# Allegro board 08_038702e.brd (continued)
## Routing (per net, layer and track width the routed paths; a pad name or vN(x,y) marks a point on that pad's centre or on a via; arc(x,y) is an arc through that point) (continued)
IO_L18_34_JX4_N: length 72.1
  TOP w0.089: U1.A7 v1(47.22,37.59)
  L6_SIG w0.089: v1(80.19,23.48) 80.06,23.6 79.3,23.6 78.92,23.22 78.92,20.3 78.54,19.92 77.78,19.92 77.4,20.3 77.4,22.33 77.01,22.71 75.36,22.71 74.98,23.1 74.98,23.98 75.36,24.37 77.67,24.37 77.9,24.6 77.9,25.35 77.67,25.58 75.64,25.58 75.11,26.11 75.11,26.76 75.64,27.29 79.19,27.29 79.43,27.52 79.43,28.58 79.19,28.81 75.64,28.81 75.11,29.34 75.11,30.69 75.64,31.22 77.54,31.22 77.78,31.46 77.78,32.39 77.54,32.62 75.74,32.62 72.77,35.59 72.75,35.59 72.67,35.67 71.32,35.67 70.05,36.94 60.6,36.94 60.52,37.02 60.24,37.02 60.16,36.94 58.49,36.94 57.73,37.7 51.69,37.7 51.53,37.54 50.45,37.54 50.29,37.7 49.81,37.7 49.43,37.32 48.21,37.32 47.57,37.95 46.94,37.95 46.74,37.75 46.74,37.5 46.8,37.43 47.06,37.43 v1(47.22,37.59)
  BOTTOM w0.089: JX4.70 80.68,23.37 80.44,23.6 80.32,23.6 v1(80.19,23.48)
IO_L18_34_JX4_P: length 72.2
  TOP w0.089: U1.B7 v1(46.22,37.59)
  L6_SIG w0.089: v1(80.19,23.98) 80.06,23.86 79.19,23.86 78.67,23.33 78.67,20.41 78.43,20.17 77.88,20.17 77.65,20.41 77.65,22.44 77.12,22.97 75.47,22.97 75.24,23.2 75.24,23.88 75.47,24.11 77.78,24.11 78.16,24.49 78.16,25.45 77.78,25.84 75.74,25.84 75.36,26.22 75.36,26.65 75.74,27.03 79.3,27.03 79.68,27.41 79.68,28.68 79.3,29.06 75.74,29.06 75.36,29.45 75.36,30.59 75.74,30.97 77.65,30.97 78.03,31.35 78.03,32.49 77.65,32.87 75.85,32.87 72.88,35.85 72.86,35.85 72.78,35.92 71.43,35.92 70.16,37.19 60.7,37.19 60.62,37.27 60.13,37.27 60.05,37.19 58.6,37.19 57.84,37.95 51.79,37.95 51.53,38.21 50.45,38.21 50.26,38.02 50.26,37.99 50.22,37.95 49.71,37.95 49.33,37.57 48.31,37.57 47.68,38.21 46.84,38.21 v1(46.22,37.59)
  BOTTOM w0.089: JX4.68 80.76,24.17 80.44,23.86 80.32,23.86 v1(80.19,23.98)
IO_L18_35_TX_D5_N: length 29.6
  TOP w0.089: U1.A17 v1(47.22,26.59) ; v6(63.6,28.89) U17.F8
  L15_SIG w0.089: v1(47.22,26.59) 47.15,26.52 46.92,26.52 46.78,26.66 46.78,26.9 46.84,26.96 47.64,26.96 49.22,25.38 49.35,25.38 50.26,24.48 50.26,24.17 50.45,23.98 50.75,23.98 52.4,22.33 58.63,22.33 58.75,22.21 62.41,22.21 64.95,24.75 64.95,26.04 65.31,26.4 65.31,26.98 65.5,27.17 65.5,27.42 65.31,27.6 65.31,27.68 65.31,27.68 65.31,28.07 64.57,28.81 64.13,28.81 63.9,28.57 63.9,28.52 63.81,28.45 63.71,28.45 63.6,28.56 v6(63.6,28.89)
IO_L18_35_TX_D5_P: length 28.3
  TOP w0.089: v6(64.4,28.09) U17.E7 ; U1.B17 v1(46.22,26.59)
  L15_SIG w0.089: v6(64.4,28.09) 64.15,28.34 64.15,28.47 64.24,28.56 64.44,28.56 65.05,27.94 65.05,27.57 64.9,27.42 64.9,27.17 65.05,27.01 65.05,26.5 64.7,26.14 64.7,24.85 62.3,22.46 58.86,22.46 58.73,22.59 52.5,22.59 50.93,24.16 50.93,24.45 50.73,24.65 50.44,24.65 49.46,25.64 49.33,25.64 47.75,27.22 46.59,27.22 46.22,26.84 v1(46.22,26.59)
IO_L19_12_JX2_N: length 74.3
  TOP w0.089: U1.AA17 v1(26.22,26.59)
  L15_SIG w0.089: v1(66.22,5.19) 66.22,4.19 65.38,3.36 65.38,3.36 65.05,3.03 64.93,3.03 63.28,1.38 35.23,1.38 32.18,4.43 32.18,4.48 32.1,4.56 32.1,5.05 32.18,5.13 32.18,7.98 29.77,10.4 28.02,10.4 27.52,10.9 22.81,10.9 21.77,11.94 21.77,16.72 22.3,17.25 22.35,17.25 22.55,17.45 22.55,24.73 22.53,24.75 22.53,25.43 22.55,25.45 22.55,25.76 23.04,26.25 25.57,26.25 25.6,26.22 26.41,26.22 26.53,26.33 26.53,26.46 26.47,26.52 26.28,26.52 v1(26.22,26.59)
  BOTTOM w0.089: JX2.90 66.33,5.8 66.05,5.53 66.05,5.35 v1(66.22,5.19)
IO_L19_12_JX2_P: length 74.4
  TOP w0.089: U1.Y17 v1(27.22,26.59)
  L15_SIG w0.089: v1(27.22,26.59) 26.85,26.59 26.79,26.52 26.79,26.23 26.52,25.96 25.5,25.96 25.46,26 23.15,26 22.81,25.66 22.81,25.34 22.79,25.32 22.79,24.85 22.81,24.83 22.81,17.34 22.46,17 22.4,17 22.02,16.62 22.02,12.05 22.91,11.16 27.62,11.16 28.13,10.65 29.88,10.65 32.44,8.09 32.44,5.03 32.36,4.95 32.36,4.67 32.44,4.59 32.44,4.53 35.34,1.63 63.17,1.63 64.82,3.28 64.95,3.28 65.97,4.3 65.97,4.43 65.71,4.68 65.46,4.68 65.33,4.81 65.33,5.06 65.46,5.19 v1(65.71,5.19)
  BOTTOM w0.089: v1(65.71,5.19) 65.84,5.32 65.84,5.57 65.53,5.88 JX2.88
IO_L19_13_JX2_N: length 74
  TOP w0.089: U1.Y20 v1(27.22,23.59)
  L15_SIG w0.089: v1(27.22,23.59) 27.35,23.45 27.48,23.45 27.59,23.35 27.59,22.46 27.31,22.18 26.97,22.18 26.55,21.76 26.55,21.45 26.29,21.19 25.96,21.19 25.58,20.81 25.58,17.48 25.55,17.46 25.55,17.45 25.07,16.97 25.07,15.37 26.11,14.33 29.11,14.33 29.75,14.97 31.06,14.97 31.7,14.33 37.14,14.33 39.17,12.3 39.17,10.03 39.46,9.73 39.46,9.49 40.42,8.53 40.8,8.53 42.36,6.97 43.97,6.97 44.73,7.73 45.92,7.73 46.15,7.5 46.15,5.85 46.68,5.32 47.78,5.32 48.31,5.85 48.31,9.99 47.78,10.52 40.92,10.52 40.69,10.75 40.69,11.06 40.92,11.28 49.22,11.28 49.46,11.05 49.46,10.16 49.98,9.63 50.6,9.63 51.36,10.4 55.17,10.4 55.81,11.03 v1(55.81,12.3)
  BOTTOM w0.089: JX2.63 55.93,11.67 55.68,11.92 55.68,12.17 v1(55.81,12.3)
IO_L19_13_JX2_P: length 74
  TOP w0.089: U1.W20 v1(28.22,23.59)
  L15_SIG w0.089: v1(55.3,12.3) 55.42,12.17 55.42,12.05 55.36,11.98 54.98,11.98 54.92,11.92 54.92,11.79 55.04,11.67 55.3,11.67 55.55,11.41 55.55,11.14 55.06,10.65 51.25,10.65 50.49,9.89 50.09,9.89 49.71,10.27 49.71,11.16 49.33,11.54 40.81,11.54 40.44,11.17 40.44,10.64 40.81,10.27 47.68,10.27 48.06,9.89 48.06,5.95 47.68,5.57 46.79,5.57 46.41,5.95 46.41,7.6 46.03,7.98 44.63,7.98 43.87,7.22 42.47,7.22 40.9,8.79 40.52,8.79 39.72,9.59 39.72,9.84 39.42,10.13 39.42,12.41 37.24,14.59 31.8,14.59 31.17,15.22 29.64,15.22 29.01,14.59 26.21,14.59 25.33,15.48 25.33,16.86 25.81,17.34 25.81,17.35 25.83,17.38 25.83,20.7 26.07,20.94 26.4,20.94 26.88,21.42 26.88,21.73 27.08,21.92 27.41,21.92 27.84,22.36 27.84,23.22 v1(28.22,23.59)
  BOTTOM w0.089: JX2.61 55.13,11.61 55.46,11.94 55.46,12.14 v1(55.3,12.3)
IO_L19_33_JX1_N: length 73
  TOP w0.089: U1.L7 v1(37.22,37.59)
  L18_SIG w0.089: v1(38.28,49.64) 38.04,49.4 38.04,48.96 38.55,48.45 38.55,47.46 38.17,47.08 37.63,47.08 37.61,47.1 36.35,47.1 35.82,47.63 35.82,48.6 36.5,49.28 36.5,49.87 36.9,50.27 41.09,50.27 41.2,50.38 41.2,51.18 41.09,51.29 36.12,51.29 35.59,51.82 35.59,53.19 35.34,53.45 34.34,53.45 34.09,53.19 34.09,49.89 33.99,49.79 33.99,49.51 34.09,49.42 34.09,49.13 34.47,48.75 34.47,46.7 34.82,46.35 34.82,46.1 35.21,45.7 37.26,45.7 37.52,45.96 37.52,46.21 37.77,46.46 38.83,46.46 39.09,46.21 39.09,44.1 38.81,43.82 38.81,32.34 38.46,32 38.44,32 38.43,31.99 37.91,31.99 37.55,32.35 37.55,44.34 37.33,44.56 37.02,44.56 36.81,44.34 36.81,40.58 36.84,40.54 36.84,37.96 v1(37.22,37.59)
  BOTTOM w0.089: JX1.20 38.33,50.32 38.03,50.02 38.03,49.89 v1(38.28,49.64)
IO_L19_33_JX1_P: length 73
  TOP w0.089: U1.M7 v1(36.22,37.59)
  L18_SIG w0.089: v1(36.22,37.59) 36.59,37.96 36.59,40.44 36.55,40.47 36.55,44.45 36.92,44.81 37.44,44.81 37.81,44.45 37.81,32.45 38.02,32.24 38.32,32.24 38.33,32.25 38.35,32.25 38.55,32.45 38.55,43.73 38.53,43.75 38.53,43.9 38.83,44.2 38.83,46.1 38.73,46.21 37.88,46.21 37.77,46.1 37.77,45.85 37.37,45.45 35.1,45.45 34.56,45.99 34.56,46.24 34.22,46.59 34.22,48.64 33.83,49.03 33.83,49.31 33.74,49.41 33.74,49.9 33.83,50 33.83,53.3 34.24,53.7 35.44,53.7 35.85,53.3 35.85,51.92 36.23,51.54 41.2,51.54 41.45,51.29 41.45,50.27 41.2,50.02 37.01,50.02 36.76,49.77 36.76,49.18 36.07,48.5 36.07,47.73 36.45,47.35 37.71,47.35 37.73,47.33 38.06,47.33 38.3,47.57 38.3,48.35 37.79,48.86 37.79,49.4 v1(37.56,49.64)
  BOTTOM w0.089: JX1.18 37.53,50.26 37.81,49.98 37.81,49.89 v1(37.56,49.64)
IO_L19_34_JX4_N: length 73.3
  TOP w0.089: U1.C3 v1(45.22,41.59)
  L6_SIG w0.089: v1(84.51,21.06) 88.7,21.06 89.33,21.7 89.33,41 88.95,41.38 87.51,41.38 87.5,41.37 87.16,41.37 87.15,41.38 85.4,41.38 85.14,41.64 84.01,41.64 83.75,41.37 81.7,41.37 81.44,41.64 79.83,41.64 79.58,41.38 78.14,41.38 77.5,40.75 75.21,40.75 74.45,41.51 63.93,41.51 63.04,42.4 61.9,42.4 60.76,41.26 57.33,41.26 57.17,41.41 55.2,41.41 55.04,41.26 52.73,41.26 52.52,41.47 52.24,41.47 52.19,41.41 49.65,41.41 49.45,41.22 45.59,41.22 v1(45.22,41.59)
  BOTTOM w0.089: v1(84.51,21.06) 84.63,21.19 84.89,21.19 85.11,20.97 JX4.75
IO_L19_34_JX4_P: length 73.2
  TOP w0.089: U1.C4 v1(45.22,40.59)
  L6_SIG w0.089: v1(45.22,40.59) 45.59,40.96 49.43,40.96 49.65,40.74 52.5,40.74 52.76,41 54.99,41 55.25,40.74 57.13,40.74 57.39,41 60.86,41 62.01,42.15 62.94,42.15 63.83,41.26 74.35,41.26 75.11,40.49 77.61,40.49 78.24,41.13 79.68,41.13 79.94,41.38 81.33,41.38 81.6,41.12 83.85,41.12 84.12,41.38 85.04,41.38 85.29,41.13 87.05,41.13 87.06,41.12 87.6,41.12 87.61,41.13 88.85,41.13 89.08,40.9 89.08,21.8 88.59,21.32 85.27,21.32 85.14,21.44 85.14,21.83 85.02,21.95 84.76,21.95 v1(84.51,21.7)
  BOTTOM w0.089: JX4.73 85.22,21.77 84.89,21.44 84.76,21.44 v1(84.51,21.7)
IO_L19_35_CTRL_OUT0: length 27.6
  TOP w0.14: v6(67.6,27.29) U17.D4 ; U1.D13 v1(44.22,31.59)
  L14_SIG w0.095: v1(44.22,31.59) 44.88,30.93 45.36,30.93 45.57,30.72 46.41,30.72 47.19,29.93 51.77,29.93 52.25,29.45 54.28,29.45 54.28,29.45 54.42,29.45 54.62,29.65 54.62,29.78 55.3,30.46 55.42,30.46 55.45,30.48 55.91,30.48 55.93,30.46 57.33,30.46 58.61,29.18 58.61,29.09 59.11,28.59 64.52,28.59 64.61,28.68 65.71,28.68 66,28.39 66.12,28.39 66.3,28.22 66.3,28.1 66.8,27.59 66.92,27.59 67.22,27.29 v6(67.6,27.29)
IO_L19_35_CTRL_OUT1: length 25.6
  TOP w0.14: v6(67.6,28.09) U17.E4 ; U1.C13 v1(45.22,31.59)
  L14_SIG w0.095: v1(45.22,31.59) 45.71,31.1 47.3,31.1 48.06,30.33 53.42,30.33 53.46,30.29 54.49,30.29 54.92,30.72 57.08,30.72 57.11,30.68 57.49,30.68 58.16,30.01 58.16,29.97 58.49,29.65 58.53,29.65 58.85,29.32 65.84,29.32 65.96,29.19 66.12,29.19 66.3,29.02 66.3,28.86 66.76,28.39 66.92,28.39 67.22,28.09 v6(67.6,28.09)
IO_L20_12_JX2_N: length 72.6
  TOP w0.089: U1.AB16 v1(25.22,27.59)
  L14_SIG w0.089: v1(25.22,27.59) 25.59,27.22 26.54,27.22 26.88,26.88 26.88,26.45 27.08,26.25 27.48,26.25 27.81,25.93 27.81,19.32 27.95,19.18 28.46,19.18 28.88,18.76 28.88,18.45 29.15,18.18 46.46,18.18 46.88,17.76 46.88,17.45 47.37,16.96 47.8,16.96 48.14,16.61 48.14,16.28 49.2,15.22 49.58,14.84 50.14,14.84 50.73,15.43 52.61,15.43 52.82,15.22 53.9,15.22 54.28,14.84 58.35,14.84 58.73,15.22 58.73,18.27 58.6,18.4 58.6,20.3 58.98,20.68 61.65,20.68 62.16,20.17 65.33,20.17 65.71,19.79 65.71,18.27 66.09,17.89 67.85,17.89 68.38,17.36 68.38,16.39 67.85,15.86 65.33,15.86 64.95,15.48 64.95,14.33 64.99,14.29 64.99,14.04 v1(65.33,13.7)
  BOTTOM w0.089: v1(65.33,13.7) 65.3,13.7 65.08,13.47 65.08,13.16 65.3,12.94 65.84,12.94 66.09,12.68 66.09,12.05 66.33,11.81 JX2.89
IO_L20_12_JX2_P: length 72.6
  TOP w0.089: U1.AB17 v1(25.22,26.59)
  L14_SIG w0.089: v1(25.22,26.59) 25.05,26.75 25.05,27.01 25.11,27.08 25.37,27.08 25.48,26.96 26.43,26.96 26.62,26.77 26.62,26.34 26.97,26 27.38,26 27.55,25.82 27.55,19.22 27.84,18.93 28.35,18.93 28.62,18.66 28.62,18.34 29.04,17.93 46.35,17.93 46.62,17.66 46.62,17.34 47.27,16.7 47.69,16.7 47.89,16.5 47.89,16.18 49.02,15.04 49.21,14.85 49.48,14.59 50.25,14.59 50.84,15.18 52.5,15.18 52.71,14.97 53.79,14.97 54.18,14.59 58.45,14.59 58.98,15.12 58.98,18.37 58.85,18.5 58.85,20.2 59.09,20.43 61.54,20.43 62.05,19.92 65.22,19.92 65.46,19.69 65.46,18.16 65.99,17.63 67.74,17.63 68.12,17.25 68.12,16.49 67.74,16.11 65.22,16.11 64.7,15.58 64.7,14.23 64.73,14.19 v1(64.73,13.7)
  BOTTOM w0.089: JX2.87 65.53,11.7 65.88,12.05 65.88,12.59 65.75,12.72 65.21,12.72 64.86,13.07 64.86,13.57 v1(64.73,13.7)
IO_L20_13_JX2_N: length 72.9
  TOP w0.089: U1.AB20 v1(25.22,23.59)
  L15_SIG w0.089: v1(55.07,8.41) 55.81,7.67 55.81,5.82 55.42,5.44 50.73,5.44 50.34,5.06 50.34,4.3 50.73,3.92 52.76,3.92 53.14,3.54 53.14,3 52.54,2.39 47.14,2.39 46.93,2.6 46.01,2.6 45.82,2.41 45.82,2.4 45.81,2.39 42.62,2.39 42.24,2.78 35.36,2.78 32.95,5.19 32.95,6.97 33.33,7.35 33.71,7.35 34.22,6.84 34.72,6.84 34.98,7.09 34.98,7.2 35.99,8.21 35.99,9.66 35.47,10.18 35.16,10.18 34.57,10.78 30.66,10.78 29.47,11.96 25.56,11.96 25.33,12.2 25.33,12.7 25.09,12.94 23.04,12.94 22.53,13.44 22.53,16.6 23.06,17.13 23.32,17.13 23.55,17.36 23.55,17.73 23.55,17.73 23.55,18.44 23.55,18.45 23.55,18.73 23.55,18.73 23.55,19.44 23.55,19.45 23.55,19.73 23.55,19.73 23.55,20.44 23.55,20.45 23.55,20.73 23.55,20.73 23.55,21.44 23.55,21.45 23.55,21.83 23.93,22.21 25.31,22.21 25.59,22.49 25.59,23.22 v1(25.22,23.59)
  BOTTOM w0.089: JX2.64 55.93,7.38 55.64,7.66 55.64,7.82 55.07,8.39 v1(55.07,8.41)
IO_L20_13_JX2_P: length 72.9
  TOP w0.089: U1.AA20 v1(26.22,23.59)
  L15_SIG w0.089: v1(26.22,23.59) 26.05,23.43 25.96,23.43 25.84,23.31 25.84,22.38 25.41,21.95 24.03,21.95 23.81,21.72 23.81,21.34 23.8,21.34 23.8,20.84 23.81,20.83 23.81,20.34 23.8,20.34 23.8,19.84 23.81,19.83 23.81,19.34 23.8,19.34 23.8,18.84 23.81,18.83 23.81,18.34 23.8,18.34 23.8,17.84 23.81,17.83 23.81,17.25 23.42,16.87 23.17,16.87 22.79,16.49 22.79,13.55 23.14,13.19 25.2,13.19 25.58,12.81 25.58,12.3 25.66,12.22 29.58,12.22 30.76,11.03 34.67,11.03 35.27,10.43 35.57,10.43 36.25,9.76 36.25,8.11 35.23,7.09 35.23,6.99 34.83,6.59 34.11,6.59 33.6,7.09 33.43,7.09 33.2,6.86 33.2,5.29 35.46,3.03 42.34,3.03 42.72,2.65 45.7,2.65 45.91,2.86 47.03,2.86 47.24,2.65 52.43,2.65 52.88,3.1 52.88,3.43 52.65,3.66 50.62,3.66 50.09,4.19 50.09,5.17 50.62,5.7 55.32,5.7 55.55,5.93 55.55,7.57 55.34,7.77 55.22,7.77 55.1,7.66 55.1,7.41 55.04,7.34 54.67,7.34 54.54,7.47 54.54,7.73 v1(54.79,7.98)
  BOTTOM w0.089: JX2.62 55.13,7.3 55.42,7.6 55.42,7.73 55.17,7.98 v1(54.79,7.98)
IO_L20_33_JX1_N: length 72.1
  TOP w0.089: U1.J5 v1(39.22,39.59)
  L3_SIG w0.089: v1(39.22,39.59) 38.88,39.92 38.88,43.73 39.5,44.35 39.85,44.35 41.71,46.21 41.71,48.6 41.96,48.85 43.34,48.85 46.28,51.8 63.04,51.8 63.43,52.18 63.43,52.57 63,52.99 63,53.31 62.79,53.52 62.79,53.96 63.3,54.46 63.3,57.01 62.93,57.39 62.4,57.39 62.03,57.01 62.03,55.61 61.65,55.23 55.17,55.23 54.79,54.85 54.79,53.83 54.41,53.45 50.79,53.45 50.75,53.4 45.98,53.4 45.72,53.15 45.18,53.15 45.18,53.14 44.9,53.14 44.89,53.15 43.66,53.15 43.27,52.76 42.72,52.76 42.51,52.54 42.18,52.54 41.94,52.77 41.94,53.11 41.96,53.13 41.96,53.7 41.96,53.7 41.96,54.19 41.96,54.19 41.96,54.59 41.58,54.97 40.67,54.97 40.44,55.2 40.44,56.75 v1(40.69,57)
  BOTTOM w0.089: JX1.25 40.73,56.21 40.44,56.5 40.44,56.75 v1(40.69,57)
IO_L20_33_JX1_P: length 72.1
  TOP w0.089: U1.K5 v1(38.22,39.59)
  L3_SIG w0.089: v1(38.22,39.59) 38.62,40 38.62,43.83 39.39,44.6 39.74,44.6 41.45,46.31 41.45,48.71 41.86,49.11 43.23,49.11 46.17,52.05 62.94,52.05 63.17,52.28 63.17,52.46 62.75,52.89 62.75,53.21 62.54,53.42 62.54,54.06 63.04,54.57 63.04,56.91 62.82,57.13 62.51,57.13 62.28,56.91 62.28,55.5 61.75,54.97 55.28,54.97 55.04,54.74 55.04,53.72 54.51,53.19 50.9,53.19 50.85,53.15 46.09,53.15 45.83,52.89 45.29,52.89 45.28,52.89 44.79,52.89 44.79,52.89 43.76,52.89 43.37,52.5 42.83,52.5 42.61,52.29 42.07,52.29 41.69,52.67 41.69,53.21 41.71,53.23 41.71,53.8 41.71,54.08 41.71,54.09 41.71,54.49 41.48,54.72 40.57,54.72 40.18,55.1 40.18,56.75 v1(39.93,57)
  BOTTOM w0.089: v1(39.93,57) 40.18,56.75 40.18,56.5 39.93,56.24 JX1.23
IO_L20_34_JX4_N: length 73.4
  TOP w0.089: U1.B4 v1(46.22,40.59)
  L6_SIG w0.089: v1(80.19,21.19) 80.48,21.19 80.55,21.12 81.11,21.12 83.87,23.88 83.87,25.76 84.25,26.14 86.39,26.14 86.92,26.67 86.92,28.92 86.39,29.45 83.72,29.45 83.49,29.68 83.49,30.99 83.72,31.22 85.78,31.22 86.16,31.6 86.16,33.13 85.78,33.51 84.25,33.51 83.87,33.89 83.87,35.41 84.11,35.65 85.27,35.65 85.65,36.03 85.65,37.12 85.27,37.5 84.24,37.5 84.2,37.54 83.02,37.54 81.5,39.05 79.17,39.05 78.75,39.48 77.4,39.48 76.89,38.97 69.52,38.97 68.74,39.75 67.32,39.75 66.86,40.22 61.74,40.22 61.38,39.86 59.47,39.86 59.11,40.22 58.49,40.22 58.22,39.94 55.25,39.94 55.21,39.99 51.58,39.99 51.53,39.94 50.45,39.94 50.41,39.99 49.74,39.99 49.59,39.84 49.32,39.84 49.17,39.99 48.37,39.99 48.14,40.22 46.59,40.22 v1(46.22,40.59)
  BOTTOM w0.089: v1(80.19,21.19) 80.29,21.29 80.51,21.29 80.83,20.97 JX4.76
IO_L20_34_JX4_P: length 73.4
  TOP w0.089: U1.B5 v1(46.22,39.59)
  L6_SIG w0.089: v1(80.19,21.7) 80.44,21.44 81.08,21.44 83.62,23.98 83.62,25.87 84.15,26.4 86.29,26.4 86.67,26.78 86.67,28.81 86.29,29.19 83.62,29.19 83.24,29.57 83.24,31.1 83.62,31.48 85.67,31.48 85.9,31.71 85.9,33.02 85.67,33.26 84.15,33.26 83.62,33.79 83.62,35.52 84,35.9 85.16,35.9 85.4,36.14 85.4,37.02 85.16,37.25 84.14,37.25 84.1,37.29 82.91,37.29 81.4,38.8 79.07,38.8 78.64,39.22 77.5,39.22 76.99,38.72 69.42,38.72 68.63,39.5 67.22,39.5 66.75,39.96 61.84,39.96 61.49,39.61 59.36,39.61 59.01,39.96 58.6,39.96 58.33,39.69 55.15,39.69 55.1,39.73 51.68,39.73 51.64,39.69 50.35,39.69 50.3,39.73 49.85,39.73 49.7,39.59 49.21,39.59 49.06,39.73 48.27,39.73 48.04,39.96 46.48,39.96 46.31,40.14 46.05,40.14 45.9,39.99 45.9,39.9 v1(46.22,39.59)
  BOTTOM w0.089: v1(80.19,21.7) 80.38,21.51 80.51,21.51 80.77,21.77 JX4.74
IO_L20_35_CTRL_OUT2: length 27.6
  TOP w0.14: v6(66.8,28.09) U17.E5 ; U1.C14 v1(45.22,29.59)
  L17_SIG w0.095: v1(45.22,29.59) 45.25,29.59 45.65,29.19 45.65,28.56 46.03,28.18 47.68,28.18 48.19,27.67 48.19,27.03 48.84,26.37 49.59,26.37 49.65,26.31 49.93,26.31 50,26.37 50.39,26.37 50.45,26.31 50.73,26.31 50.8,26.37 51.19,26.37 51.25,26.31 51.53,26.31 51.6,26.37 54.12,26.37 54.14,26.39 54.55,26.39 54.75,26.2 54.75,26.19 55.29,25.64 57.15,25.64 57.79,26.27 60.19,26.27 60.27,26.19 66.12,26.19 66.3,26.37 66.3,26.48 66.81,26.99 66.92,26.99 67.1,27.17 67.1,27.28 67.17,27.34 67.17,27.72 v6(66.8,28.09)
IO_L20_35_CTRL_OUT3: length 22.6
  TOP w0.14: v6(66,28.09) U17.E6 ; U1.B14 v1(46.22,29.59)
  L17_SIG w0.095: v6(66,28.09) 65.7,27.79 60.19,27.79 60.14,27.84 56.95,27.84 56.83,27.95 56.83,27.95 56.63,28.15 56.63,28.3 56.24,28.68 54.41,28.68 53.65,27.92 49.07,27.92 47.93,29.06 46.79,29.06 46.26,29.59 v1(46.22,29.59)
IO_L21_12_JX2_N: length 73.8
  TOP w0.089: U1.AC16 v1(24.22,27.59)
  L6_SIG w0.089: v1(68.76,12.68) 68.76,13.7 68.38,14.08 66.71,14.08 66.47,14.31 66.47,15.09 66.85,15.48 68.36,15.48 68.4,15.52 68.68,15.52 68.73,15.48 70.03,15.48 70.41,15.86 70.41,16.24 70.03,16.62 66.85,16.62 66.47,17 66.47,17.63 66.09,18.02 65.58,18.02 65.2,17.63 65.2,15.2 64.97,14.97 64.29,14.97 64.06,15.2 64.06,16.52 63.58,17 62.79,17 62.41,16.62 62.41,15.48 62.03,15.09 60.35,15.09 60.14,14.88 59.74,14.88 59.36,15.27 59.36,17.25 58.98,17.63 57.84,17.63 57.46,17.25 56.06,17.25 55.84,17.48 55.54,17.48 55.32,17.25 50.93,17.25 50.73,17.45 50.45,17.45 50.26,17.25 50.13,17.25 49.93,17.45 49.65,17.45 49.46,17.25 48.54,17.25 47.55,18.25 37.01,18.25 36.81,18.45 36.81,18.83 36.46,19.18 36.08,19.18 35.81,19.45 35.81,19.83 35.46,20.18 35.08,20.18 33.81,21.45 33.81,21.83 33.46,22.18 33.08,22.18 32.81,22.45 32.81,22.83 32.46,23.18 32.08,23.18 31.81,23.45 31.81,23.83 31.46,24.18 31.08,24.18 30.81,24.45 30.81,24.83 30.46,25.18 30.08,25.18 29.81,25.45 29.81,25.83 29.44,26.2 29.39,26.25 27.08,26.25 26.81,26.52 26.81,26.83 26.46,27.18 24.62,27.18 v1(24.22,27.59)
  BOTTOM w0.089: v1(68.76,12.68) 68.51,12.43 68.51,12.05 68.73,11.82 JX2.95
IO_L21_12_JX2_P: length 73.8
  TOP w0.089: U1.AC17 v1(24.22,26.59)
  L6_SIG w0.089: v1(24.22,26.59) 24.55,26.93 26.35,26.93 26.55,26.73 26.55,26.42 26.97,26 29.26,26 29.34,25.93 29.35,25.93 29.55,25.73 29.55,25.35 29.97,24.93 30.35,24.93 30.55,24.73 30.55,24.35 30.97,23.93 31.35,23.93 31.55,23.73 31.55,23.35 31.97,22.93 32.35,22.93 32.55,22.73 32.55,22.35 32.97,21.93 33.35,21.93 33.55,21.73 33.55,21.35 34.97,19.93 35.35,19.93 35.55,19.73 35.55,19.35 35.97,18.93 36.35,18.93 36.55,18.73 36.55,18.35 36.9,18 47.44,18 48.44,17 49.43,17 49.65,16.78 49.93,16.78 50.15,17 50.23,17 50.45,16.78 50.73,16.78 50.95,17 55.29,17 55.54,16.75 55.84,16.75 56.09,17 57.56,17 57.94,17.38 58.87,17.38 59.11,17.15 59.11,15.16 59.64,14.63 60.24,14.63 60.45,14.84 62.13,14.84 62.66,15.37 62.66,16.51 62.9,16.75 63.48,16.75 63.81,16.42 63.81,15.09 64.19,14.71 65.08,14.71 65.46,15.09 65.46,17.53 65.69,17.76 65.99,17.76 66.22,17.53 66.22,16.89 66.75,16.36 69.92,16.36 70.16,16.13 70.16,15.96 69.92,15.73 68.83,15.73 68.79,15.77 68.3,15.77 68.25,15.73 66.75,15.73 66.22,15.2 66.22,14.21 66.6,13.82 68.27,13.82 68.51,13.59 68.51,13.57 68.38,13.44 68.38,13.32 68.51,13.19 68.51,13.06 68.38,12.94 68.38,12.81 68.25,12.68 v1(68.12,12.68)
  BOTTOM w0.089: v1(68.12,12.68) 68.29,12.52 68.29,12.07 67.93,11.71 JX2.93
IO_L21_13_JX2_N: length 72.2
  TOP w0.089: U1.AC19 v1(24.22,24.59)
  L14_SIG w0.089: v3(58.35,13.06) 58.09,12.81 58.09,11.92 57.82,11.65 56.94,11.65 56.56,11.27 56.56,10.61 56.94,10.22 61.03,10.22 61.27,10.46 61.27,10.83 61.8,11.36 63.93,11.36 64.31,10.98 64.31,10.22 63.93,9.84 62.13,9.84 61.9,9.61 61.9,8.24 61.01,7.35 53.9,7.35 53.52,7.73 53.52,11.69 53.29,11.92 48.28,11.92 47.75,12.45 47.75,13.2 47.56,13.39 46.97,13.39 46.28,14.08 39.89,14.08 38.75,15.22 31.82,15.22 31.32,15.73 27.61,15.73 26.47,16.87 25.83,16.87 25.55,17.15 25.55,20.73 25.35,20.93 25.04,20.93 24.62,21.34 24.62,24.51 24.54,24.59 v1(24.22,24.59)
  L19_GND w0.089: v4(58.22,12.43) 58.22,12.94 v3(58.35,13.06)
  BOTTOM w0.089: v4(58.22,12.43) 58.05,12.26 58.05,12.05 58.33,11.77 JX2.69
IO_L21_13_JX2_P: length 72.3
  TOP w0.089: U1.AC18 v1(24.22,25.59)
  L14_SIG w0.089: v1(24.22,25.59) 24.88,24.93 24.88,21.45 25.15,21.18 25.46,21.18 25.81,20.83 25.81,17.26 25.94,17.13 26.57,17.13 27.72,15.98 31.42,15.98 31.93,15.48 38.86,15.48 40,14.33 46.39,14.33 47.07,13.65 47.66,13.65 48.01,13.3 48.01,12.55 48.39,12.17 53.39,12.17 53.77,11.79 53.77,7.83 54.01,7.6 60.91,7.6 61.65,8.34 61.65,9.72 62.03,10.1 63.83,10.1 64.06,10.33 64.06,10.87 63.83,11.11 61.9,11.11 61.52,10.73 61.52,10.35 61.14,9.97 56.84,9.97 56.31,10.5 56.31,11.37 56.84,11.9 57.71,11.9 57.84,12.02 57.84,12.81 v3(57.58,13.06)
  L19_GND w0.089: v4(57.71,12.43) 57.71,12.94 v3(57.58,13.06)
  BOTTOM w0.089: v4(57.71,12.43) 57.84,12.3 57.84,12.05 57.53,11.74 JX2.67
IO_L21_33_JX1_N: length 73.8
  TOP w0.089: U1.L8 v1(37.22,36.59)
  L3_SIG w0.089: v1(37.22,36.59) 36.84,36.22 36.84,35.43 37.1,35.18 45.28,35.18 45.55,35.45 45.55,42.93 45.48,43 44.95,43 44.88,42.93 44.88,37.45 44.88,37.44 44.88,36.73 44.88,36.73 44.88,36.45 44.88,36.44 44.88,36.33 44.55,36 44.38,36 44.38,36 43.97,36 43.62,36.34 43.62,36.39 43.61,36.4 43.61,39.88 43.51,39.99 42.96,39.99 42.85,39.88 42.85,36.4 42.81,36.36 42.81,36.34 42.46,36 41.97,36 41.62,36.34 41.62,38.83 41.46,39 41.08,39 40.82,38.74 40.82,36.4 40.81,36.39 40.81,36.34 40.46,36 37.97,36 37.62,36.34 37.62,43.88 38.66,44.92 38.66,51.01 39.57,51.92 43.72,51.92 44.12,51.52 44.12,51.06 43.72,50.65 40.8,50.65 40.57,50.42 40.57,49.77 v1(40.69,49.64)
  BOTTOM w0.089: JX1.26 40.73,50.18 40.5,49.96 40.5,49.83 v1(40.69,49.64)
IO_L21_33_JX1_P: length 73.9
  TOP w0.089: U1.M8 v1(36.22,36.59)
  L3_SIG w0.089: v1(36.22,36.59) 36.59,36.22 36.59,35.33 36.99,34.92 45.39,34.92 45.81,35.34 45.81,43.03 45.59,43.25 44.84,43.25 44.62,43.03 44.62,37.34 44.63,37.34 44.63,36.84 44.62,36.83 44.62,36.5 44.38,36.25 44.08,36.25 43.88,36.45 43.88,36.49 43.87,36.51 43.87,39.99 43.61,40.24 42.85,40.24 42.6,39.99 42.6,36.51 42.55,36.46 42.55,36.45 42.35,36.25 42.08,36.25 41.88,36.45 41.88,38.94 41.57,39.25 40.97,39.25 40.57,38.85 40.57,36.51 40.55,36.49 40.55,36.45 40.35,36.25 38.08,36.25 37.88,36.45 37.88,43.78 38.91,44.81 38.91,50.91 39.68,51.67 43.61,51.67 43.87,51.42 43.87,51.16 43.61,50.91 40.69,50.91 40.31,50.53 40.31,49.86 v1(40.09,49.64)
  BOTTOM w0.089: JX1.24 39.93,50.28 40.29,49.92 40.29,49.83 v1(40.09,49.64)
IO_L21_34_JX4_N: length 73.4
  TOP w0.089: U1.A5 v1(47.22,39.59)
  L18_SIG w0.089: v1(47.22,39.59) 46.69,39.59 46.35,39.92 45.96,39.92 45.9,39.99 45.81,40.08 45.81,43.6 45.83,43.62 45.88,43.67 45.88,43.73 46.15,44 46.15,45.55 45.65,46.06 45.65,46.74 47.53,48.62 54.28,48.62 54.66,48.24 58.62,48.24 58.85,48.01 58.85,46.97 59.49,46.34 62.28,46.34 65.46,43.16 65.46,42.65 67.11,41 70.79,41 71.3,40.49 71.3,39.61 73.33,37.57 73.33,32.6 72.19,31.46 72.19,29.85 74.29,27.74 74.29,24.11 74.68,23.73 76.9,23.73 77.28,23.35 77.28,22.71 77.66,22.33 80.08,22.33 81.33,21.09 81.33,20.58 82.12,19.79 83.87,19.79 84.13,19.54 84.13,19.29 84.19,19.22 84.32,19.22 v1(84.51,19.41)
  BOTTOM w0.089: JX4.79 85.18,19.37 84.89,19.67 84.76,19.67 v1(84.51,19.41)
IO_L21_34_JX4_P: length 73.5
  TOP w0.089: U1.B6 v1(46.22,38.59)
  L18_SIG w0.089: v1(84.51,20.05) 82.22,20.05 81.59,20.68 81.59,21.19 80.19,22.59 77.77,22.59 77.53,22.82 77.53,23.45 77,23.98 74.78,23.98 74.55,24.22 74.55,27.85 72.44,29.95 72.44,31.35 73.59,32.49 73.59,37.68 71.55,39.71 71.55,40.6 70.9,41.26 67.21,41.26 65.71,42.76 65.71,43.27 62.39,46.59 59.59,46.59 59.11,47.08 59.11,48.11 58.73,48.5 54.77,48.5 54.39,48.88 47.42,48.88 45.39,46.84 45.39,45.96 45.9,45.45 45.9,44.11 45.68,43.89 45.63,43.84 45.63,43.81 45.55,43.74 45.55,39.97 45.85,39.67 45.85,39.47 46.22,39.11 v1(46.22,38.59)
  BOTTOM w0.089: v1(84.51,20.05) 84.67,19.88 84.89,19.88 85.18,20.17 JX4.77
IO_L21_35_CTRL_OUT4: length 23.6
  TOP w0.14: v6(66,28.89) U17.F6 ; U1.A15 v1(47.22,28.59)
  L17_SIG w0.095: v6(66,28.89) 66.37,28.52 66.37,27.56 66.3,27.49 66.3,27.17 66.12,26.99 60.25,26.99 60.21,27.03 57.96,27.03 57.71,27.29 56.38,27.29 56.33,27.24 55.25,27.24 55.2,27.29 53.32,27.29 52.94,26.91 51.62,26.91 51.53,26.99 51.25,26.99 51.17,26.91 50.82,26.91 50.73,26.99 50.45,26.99 50.37,26.91 50.02,26.91 49.93,26.99 49.5,26.99 49.2,27.29 49.2,27.48 48.09,28.59 v1(47.22,28.59)
IO_L21_35_CTRL_OUT5: length 22.9
  TOP w0.14: v6(66.8,28.89) U17.F5 ; U1.A14 v1(47.22,29.59)
  L17_SIG w0.095: v6(66.8,28.89) 66.37,29.32 65.58,29.32 65.08,28.81 64.74,28.81 64.52,28.59 59.9,28.59 59.62,28.3 57.67,28.3 57.2,28.77 56.73,28.77 56.53,28.97 56.53,29.32 56.27,29.58 55.54,29.58 55.53,29.58 54.71,29.58 53.9,28.77 49.11,28.77 48.3,29.59 v1(47.22,29.59)
IO_L22_12_JX2_N: length 74.1
  TOP w0.089: U1.AA14 v1(26.22,29.59)
  L17_SIG w0.089: v3(68.76,7.47) 68.76,7.81 68.57,8 68.57,8.19 68.27,8.49 67.72,8.49 67.36,8.85 67.36,10.12 66.47,11.01 66.47,12.83 67.59,13.95 70.66,13.95 71.05,14.33 71.05,17.53 71.28,17.76 71.68,17.76 72.06,18.14 72.06,19.67 71.68,20.05 71.68,22.21 71.3,22.59 62.43,22.59 62.05,22.21 61.12,22.21 60.74,22.59 60.74,22.71 60.36,23.1 49.07,23.1 48.82,23.35 47.45,23.35 47.35,23.25 43.08,23.25 42.88,23.45 42.88,23.81 42.44,24.25 42.08,24.25 41.88,24.45 41.88,24.81 41.44,25.25 41.08,25.25 40.88,25.45 40.88,25.81 40.44,26.25 31.91,26.25 31.81,26.35 31.81,26.83 31.8,26.84 31.8,27.34 31.81,27.34 31.81,27.83 31.46,28.18 30,28.18 29.81,28.37 29.81,28.83 29.45,29.19 26.81,29.19 26.78,29.22 26.59,29.22 v1(26.22,29.59)
  L19_GND w0.089: v4(68.63,7.98) 68.63,7.6 v3(68.76,7.47)
  BOTTOM w0.089: JX2.96 68.73,7.38 68.51,7.6 68.51,7.86 v4(68.63,7.98)
IO_L22_12_JX2_P: length 74.1
  TOP w0.089: U1.AA15 v1(26.22,28.59)
  L17_SIG w0.089: v3(68.12,7.47) 68.12,7.81 68.31,8 68.31,8.08 68.16,8.24 67.62,8.24 67.11,8.74 67.11,10.01 66.22,10.9 66.22,12.94 67.49,14.21 70.56,14.21 70.79,14.44 70.79,17.63 71.17,18.02 71.57,18.02 71.81,18.25 71.81,19.56 71.43,19.94 71.43,22.1 71.19,22.33 62.54,22.33 62.16,21.95 61.01,21.95 60.48,22.48 60.48,22.61 60.25,22.84 48.97,22.84 48.71,23.1 47.56,23.1 47.46,23 42.97,23 42.62,23.34 42.62,23.7 42.33,24 41.97,24 41.62,24.34 41.62,24.7 41.33,25 40.97,25 40.62,25.34 40.62,25.7 40.33,26 31.8,26 31.55,26.25 31.55,26.73 31.55,26.73 31.55,27.45 31.55,27.45 31.55,27.73 31.35,27.92 29.89,27.92 29.55,28.27 29.55,28.73 29.34,28.94 26.7,28.94 26.68,28.96 26.48,28.96 26.38,29.06 26.21,29.06 26.09,28.94 26.09,28.81 26.22,28.68 v1(26.22,28.59)
  L19_GND w0.089: v4(68.12,7.98) v3(68.12,7.47)
  BOTTOM w0.089: JX2.94 67.93,7.28 68.25,7.6 68.25,7.86 v4(68.12,7.98)
IO_L22_13_JX2_N: length 74.1
  TOP w0.089: U1.AB19 v1(25.22,24.59)
  L15_SIG w0.089: v3(58.22,9.13) 58.22,8.24 58.09,8.11 58.09,7.22 57.46,6.59 57.08,6.59 56.31,7.35 56.31,7.98 55.38,8.92 54.8,8.92 54.72,9 53.86,9 53.77,8.91 53.77,6.46 53.52,6.2 49.46,6.2 49.07,5.82 49.07,3.69 48.67,3.28 42.87,3.28 42.75,3.41 39.3,3.41 38.91,3.79 38.91,4.05 38.54,4.43 38.02,4.43 37.64,4.05 37.64,3.81 37.24,3.41 36.25,3.41 35.87,3.79 35.87,5.7 35.6,5.96 35.6,6.7 36.25,7.35 38.3,7.35 38.53,7.58 38.53,11.05 38.3,11.28 35.63,11.28 35.1,11.81 32.29,11.81 30.74,13.36 30.05,13.36 29.75,13.06 25.85,13.06 23.67,15.24 23.67,16.57 24.55,17.45 24.55,17.62 24.56,17.63 24.56,20.81 25.01,21.25 25.35,21.25 25.55,21.45 25.55,21.78 26.02,22.25 26.35,22.25 26.55,22.45 26.55,23.73 26.35,23.93 25.77,23.93 25.59,24.11 25.59,24.22 v1(25.22,24.59)
  L19_GND w0.089: v4(58.22,8.62) v3(58.22,9.13)
  BOTTOM w0.089: JX2.70 58.33,7.33 58.05,7.6 58.05,8.45 v4(58.22,8.62)
IO_L22_13_JX2_P: length 74.1
  TOP w0.089: U1.AA19 v1(26.22,24.59)
  L15_SIG w0.089: v1(26.22,24.59) 25.86,24.23 25.86,24.2 25.88,24.18 26.46,24.18 26.81,23.83 26.81,22.34 26.46,22 26.13,22 25.81,21.68 25.81,21.34 25.46,21 25.11,21 24.82,20.7 24.82,17.53 24.81,17.52 24.81,17.34 23.93,16.47 23.93,15.35 25.96,13.32 29.64,13.32 29.94,13.62 30.85,13.62 32.39,12.07 35.21,12.07 35.74,11.54 38.41,11.54 38.79,11.16 38.79,7.47 38.41,7.09 36.35,7.09 35.85,6.59 35.85,6.07 36.12,5.8 36.12,3.9 36.35,3.66 37.14,3.66 37.39,3.92 37.39,4.16 37.91,4.68 38.65,4.68 39.17,4.16 39.17,3.9 39.4,3.66 42.85,3.66 42.98,3.54 48.57,3.54 48.82,3.79 48.82,5.93 49.35,6.46 53.41,6.46 53.52,6.56 53.52,9.01 53.76,9.25 54.82,9.25 54.9,9.17 55.49,9.17 56.57,8.09 56.57,7.45 57.18,6.84 57.35,6.84 57.84,7.33 57.84,7.6 57.71,7.73 57.71,7.86 57.84,7.98 57.84,8.21 57.96,8.34 57.96,8.74 57.9,8.81 57.77,8.81 57.71,8.74 57.46,8.74 57.39,8.81 57.39,8.93 v3(57.58,9.13)
  L19_GND w0.089: v3(57.58,9.13) 57.71,9 v4(57.71,8.62)
  BOTTOM w0.089: JX2.68 57.53,7.29 57.84,7.6 57.84,8.49 v4(57.71,8.62)
IO_L22_33_JX1_N: length 72.5
  TOP w0.089: U1.J6 v1(39.22,38.59)
  L3_SIG w0.089: v1(43.11,57.13) 43.11,55.04 43.3,54.85 53.52,54.85 53.9,55.23 53.9,55.99 54.28,56.37 60.78,56.37 61.14,56.73 61.14,57.77 61.52,58.15 64.95,58.15 65.33,57.77 65.33,57.28 64.57,56.52 64.57,55.71 65.33,54.95 65.33,54.23 64.7,53.6 64.7,53.3 64.91,53.09 65,53.09 65.02,53.07 65.38,52.7 65.38,52.16 65.33,52.11 65.33,51.28 64.95,50.9 47.75,50.9 44.86,48.01 44.86,47.67 43.99,46.81 43.65,46.81 40.81,43.96 40.81,40.34 40.46,40 40.15,40 39.81,39.65 39.81,39.34 39.35,38.89 38.88,38.89 38.68,38.7 38.68,38.57 38.79,38.46 39.09,38.46 v1(39.22,38.59)
  BOTTOM w0.089: v1(43.11,57.13) 42.85,56.88 42.85,56.5 43.13,56.22 JX1.31
IO_L22_33_JX1_P: length 72.4
  TOP w0.089: U1.K6 v1(38.22,38.59)
  L3_SIG w0.089: v1(38.22,38.59) 38.77,39.15 39.25,39.15 39.55,39.45 39.55,39.76 40.04,40.25 40.35,40.25 40.55,40.45 40.55,44.07 43.55,47.06 43.89,47.06 44.6,47.78 44.6,48.12 47.64,51.15 64.84,51.15 65.08,51.39 65.08,52.22 65.13,52.27 65.13,52.6 64.91,52.81 64.89,52.83 64.8,52.83 64.44,53.19 64.44,53.7 65.08,54.34 65.08,54.85 64.31,55.61 64.31,56.62 65.08,57.39 65.08,57.66 64.84,57.89 61.63,57.89 61.39,57.66 61.39,56.62 60.89,56.12 54.39,56.12 54.15,55.88 54.15,55.12 53.62,54.59 43.4,54.59 43.19,54.59 42.85,54.93 42.85,56.24 42.6,56.5 42.34,56.5 42.22,56.62 42.22,56.88 v1(42.47,57.13)
  BOTTOM w0.089: v1(42.47,57.13) 42.64,56.97 42.64,56.41 42.33,56.1 JX1.29
IO_L22_34_JX4_N: length 72.8
  TOP w0.089: U1.A3 v1(47.22,41.59)
  L18_SIG w0.089: v1(80.17,19.43) 80.19,19.41 80.19,19.29 80.06,19.16 79.94,19.16 79.81,19.29 79.81,19.67 79.68,19.79 78.31,19.79 77.42,20.68 76.1,20.68 75.62,20.2 75.62,15.73 75.24,15.35 73.46,15.35 73.08,15.73 73.08,19.16 72.7,19.54 71.68,19.54 71.3,19.92 71.3,33.38 66.73,37.95 66.73,39.25 60.97,45.01 60.97,45.21 60.77,45.4 58.87,45.4 58.47,45.81 58.47,46.61 58.37,46.72 50.6,46.72 50.2,47.12 50.2,47.63 50.09,47.73 48.19,47.73 47.68,47.23 47.68,44.56 46.81,43.69 46.81,41.25 46.82,41.23 46.97,41.23 47.02,41.28 47.02,41.39 v1(47.22,41.59)
  BOTTOM w0.089: JX4.80 80.78,19.37 80.51,19.64 80.38,19.64 v1(80.17,19.43)
IO_L22_34_JX4_P: length 72.8
  TOP w0.089: U1.A4 v1(47.22,40.59)
  L18_SIG w0.089: v1(47.22,40.59) 46.84,40.96 46.74,40.96 46.55,41.15 46.55,43.79 47.42,44.66 47.42,47.33 48.08,47.99 50.2,47.99 50.45,47.73 50.45,47.23 50.7,46.97 58.47,46.97 58.73,46.72 58.73,45.91 58.98,45.66 60.88,45.66 61.22,45.31 61.22,45.11 66.98,39.35 66.98,38.06 71.55,33.49 71.55,20.03 71.79,19.79 72.8,19.79 73.33,19.26 73.33,15.83 73.56,15.6 75.13,15.6 75.36,15.83 75.36,20.3 76,20.94 77.52,20.94 78.41,20.05 v1(80.19,20.05)
  BOTTOM w0.089: JX4.78 80.69,20.17 80.44,19.92 80.32,19.92 v1(80.19,20.05)
IO_L22_35_CTRL_OUT6: length 29.5
  TOP w0.14: U1.C12 v1(45.22,32.59) ; v6(67.6,28.89) U17.F4
  L4_SIG w0.095: v1(45.22,32.59) 45.3,32.59 45.9,31.99 47.68,31.99 48.21,32.52 51.41,32.52 52.53,33.64 53.44,33.64 54.08,34.27 57.33,34.27 57.61,33.99 60.52,33.99 60.9,33.62 60.9,33.57 61.07,33.39 61.14,33.39 61.14,33.39 62.02,33.39 62.5,32.92 62.5,32.77 62.67,32.59 62.82,32.59 63.3,32.12 63.3,31.97 63.47,31.79 63.72,31.79 64.1,32.16 64.1,32.22 64.27,32.39 65.52,32.39 65.7,32.22 65.87,32.39 66.12,32.39 66.3,32.22 66.3,32.16 66.87,31.59 66.92,31.59 67.3,31.22 67.3,31.17 67.67,30.79 67.72,30.79 67.9,30.62 67.9,30.37 67.87,30.34 67.87,29.17 v6(67.6,28.89)
IO_L22_35_CTRL_OUT7: length 24.6
  TOP w0.14: U1.B12 v1(46.22,32.59) ; v6(67.6,30.49) U17.G4
  L14_SIG w0.095: v1(46.22,32.59) 46.76,33.13 48.31,33.13 48.69,33.51 58.98,33.51 59.87,32.62 60.24,32.62 60.27,32.59 60.52,32.59 60.55,32.62 61.04,32.62 61.07,32.59 61.32,32.59 61.35,32.62 61.84,32.62 61.87,32.59 62.12,32.59 62.15,32.62 62.64,32.62 62.67,32.59 62.92,32.59 62.95,32.62 63.44,32.62 63.47,32.59 63.72,32.59 64.06,32.25 64.06,31.86 65.08,30.84 67.25,30.84 v6(67.6,30.49)
IO_L23_12_JX2_N: length 72.7
  TOP w0.089: U1.Y15 v1(27.22,28.59)
  L14_SIG w0.089: v1(27.22,28.59) 27.59,28.22 27.78,28.22 27.82,28.18 28.46,28.18 28.81,27.83 28.81,20.48 29.11,20.18 29.46,20.18 29.81,19.83 29.81,19.48 30.04,19.25 47.69,19.25 48.31,18.63 48.31,17.89 49.46,16.74 49.46,16.17 49.7,15.93 57.17,15.93 57.46,16.22 57.46,21.32 58.6,22.46 64.55,22.46 65.08,21.93 65.08,21.8 65.31,21.57 67.24,21.57 67.74,21.06 67.74,20.05 68.12,19.67 70.92,19.67 71.3,19.29 71.3,17.18 71.28,17.17 71.28,16.35 70.92,15.98 70.16,15.98 69.78,15.6 69.78,14.84 70.03,14.59 70.03,13.65 70.16,13.52 v1(70.16,13.19)
  BOTTOM w0.089: JX2.99 70.33,11.75 70.03,12.05 70.03,13.06 v1(70.16,13.19)
IO_L23_12_JX2_P: length 72.8
  TOP w0.089: U1.Y16 v1(27.22,27.59)
  L14_SIG w0.089: v1(69.65,13.19) 69.65,13.52 69.78,13.65 69.78,14.48 69.52,14.74 69.52,15.71 70.05,16.24 70.81,16.24 71.03,16.45 71.03,17.27 71.05,17.29 71.05,19.18 70.81,19.41 68.02,19.41 67.49,19.94 67.49,20.96 67.13,21.32 65.2,21.32 64.82,21.7 64.82,21.83 64.44,22.21 58.7,22.21 57.71,21.21 57.71,16.11 57.27,15.67 49.6,15.67 49.2,16.07 49.2,16.64 48.06,17.78 48.06,18.52 47.58,19 29.93,19 29.55,19.38 29.55,19.73 29.35,19.93 29,19.93 28.55,20.38 28.55,27.73 28.35,27.93 27.71,27.93 27.68,27.96 27.48,27.96 27.34,28.11 27.24,28.11 27.12,27.98 27.12,27.69 v1(27.22,27.59)
  BOTTOM w0.089: v1(69.65,13.19) 69.78,13.06 69.78,12.05 69.53,11.8 JX2.97
IO_L23_13_JX2_N: length 74.2
  TOP w0.089: U1.W19 v1(28.22,24.59)
  L3_SIG w0.089: v3(60.63,10.65) 60.38,10.4 60.38,10.16 60.1,9.89 59.46,9.89 59.37,9.97 59.09,9.97 58.85,9.73 58.85,8.16 58.79,8.1 58.79,7.54 57.71,6.46 55.93,6.46 55.55,6.08 55.55,5.7 55.17,5.32 53.52,5.32 53.14,5.7 45.01,5.7 44.63,6.08 44.63,6.97 45.01,7.35 50.22,7.35 50.85,7.98 50.85,9 50.47,9.38 49.78,9.38 49.2,9.96 49.2,10.4 48.82,10.78 40.08,10.78 39.3,11.56 39.3,15.22 38.91,15.6 30.91,15.6 30.15,16.36 30.15,16.62 29.62,17.14 29.62,22.93 29.92,23.22 33.58,23.22 33.71,23.35 33.71,24.26 33.63,24.34 33.63,24.7 33.37,24.96 28.59,24.96 v1(28.22,24.59)
  L19_GND w0.089: v4(60.63,11.16) v3(60.63,10.65)
IO_L23_13_JX2_P: length 74.2
  TOP w0.089: U1.W18 v1(28.22,25.59)
  L3_SIG w0.089: v1(28.22,25.59) 28.22,25.38 28.17,25.33 28.17,25.2 28.26,25.12 28.38,25.12 28.48,25.22 33.47,25.22 33.88,24.81 33.88,24.45 33.96,24.37 33.96,23.24 33.69,22.97 30.02,22.97 29.88,22.82 29.88,17.25 30.41,16.72 30.41,16.47 31.02,15.86 39.02,15.86 39.55,15.33 39.55,11.67 40.18,11.03 48.93,11.03 49.46,10.5 49.46,10.07 49.89,9.63 50.58,9.63 51.11,9.1 51.11,7.88 50.32,7.09 45.12,7.09 44.88,6.86 44.88,6.18 45.12,5.95 53.24,5.95 53.62,5.57 55.06,5.57 55.3,5.8 55.3,6.18 55.83,6.71 57.58,6.71 58.54,7.67 58.54,8.21 58.6,8.27 58.6,9.89 58.94,10.22 59.48,10.22 59.56,10.14 60,10.14 60.12,10.27 60.12,10.4 v3(59.87,10.65)
  L19_GND w0.089: v4(60,11.16) 60,10.78 v3(59.87,10.65)
IO_L23_33_JX1_N: length 72
  TOP w0.089: U1.N6 v1(35.22,38.59)
  L7_SIG w0.089: v1(43.11,49.64) 42.85,49.89 42.85,50.27 42.34,50.78 38.51,50.78 38.28,51.01 38.28,51.42 38.53,51.67 41.2,51.67 41.45,51.92 43.57,51.92 43.66,51.84 44.2,51.84 44.28,51.92 45.39,51.92 45.77,52.31 45.77,54.46 46.15,54.85 48.96,54.85 49.33,55.22 49.33,55.74 48.96,56.12 46.53,56.12 46.15,56.5 46.15,57.62 45.9,57.87 45.9,58.68 46.03,58.8 46.03,59.4 45.5,59.93 44.65,59.93 44.12,59.4 44.12,54.95 43.89,54.72 38.51,54.72 38.28,54.95 38.28,55.99 37.9,56.37 34.72,56.37 34.22,55.86 32.18,55.86 31.68,55.35 31.68,54.87 32.08,54.46 35.25,54.46 35.36,54.36 35.36,50.93 35.89,50.4 36.37,50.4 36.5,50.27 36.5,46.21 35.61,45.32 35.61,38.72 35.48,38.59 v1(35.22,38.59)
  BOTTOM w0.089: v1(43.11,49.64) 42.81,49.93 42.81,50.11 43.13,50.42 JX1.32
IO_L23_33_JX1_P: length 72.1
  TOP w0.089: U1.N7 v1(35.22,37.59)
  L7_SIG w0.089: v1(35.22,37.59) 35.87,38.24 35.87,45.22 36.76,46.1 36.76,50.38 36.48,50.65 35.99,50.65 35.61,51.04 35.61,54.46 35.36,54.72 32.19,54.72 31.93,54.98 31.93,55.25 32.29,55.61 34.32,55.61 34.83,56.12 37.79,56.12 38.03,55.88 38.03,54.85 38.41,54.46 43.99,54.46 44.38,54.85 44.38,59.29 44.76,59.67 45.39,59.67 45.77,59.29 45.77,58.91 45.65,58.78 45.65,57.77 45.9,57.51 45.9,56.39 46.43,55.86 48.85,55.86 49.07,55.64 49.07,55.32 48.85,55.1 46.05,55.1 45.52,54.57 45.52,52.41 45.29,52.18 44.18,52.18 44.09,52.09 43.76,52.09 43.68,52.18 41.35,52.18 41.09,51.92 38.43,51.92 38.03,51.52 38.03,50.91 38.41,50.53 42.24,50.53 42.6,50.17 42.6,49.89 v1(42.34,49.64)
  BOTTOM w0.089: v1(42.34,49.64) 42.6,49.89 42.6,50.02 42.33,50.29 JX1.30
IO_L23_34_CTRL_IN0: length 25.6
  TOP w0.14: U22.13 54.81,30.48 54.28,29.95 v1(54.28,29.79) ; U1.C2 v1(45.22,42.59)
  L15_SIG w0.095: v1(45.22,42.59) 45.22,42.6 45.88,43.27 45.88,43.73 46.07,43.93 46.36,43.93 46.42,43.86 46.46,43.86 47.07,43.25 49.54,43.25 49.65,43.14 49.93,43.14 50.04,43.25 50.34,43.25 50.51,43.08 52.97,43.08 53.77,42.27 53.77,34.14 54.92,33 54.92,30.42 v1(54.28,29.79)
IO_L23_34_CTRL_IN1: length 21.6
  TOP w0.14: v1(54.28,30.72) 54.54,30.98 U22.12 ; U1.B1 v1(46.22,43.59)
  L15_SIG w0.095: v1(46.22,43.59) 46.22,43.48 46.67,43.03 49.34,43.03 50.09,42.27 52.76,42.27 53.52,41.51 53.52,34.02 54.66,32.87 54.66,31.1 v1(54.28,30.72)
IO_L23_35_SPI_CLK: length 24.7
  TOP w0.14: v6(66.8,32.09) U17.J5 ; U1.B11 v1(46.22,33.59)
  L14_SIG w0.095: v6(66.8,32.09) 66.8,31.93 66.47,31.6 65.46,31.6 64.95,32.11 64.95,33.76 64.7,34.02 57.33,34.02 57.13,34.22 55.25,34.22 55.05,34.02 51.79,34.02 51.53,34.27 50.74,34.27 50.73,34.28 50.45,34.28 50.44,34.27 49.7,34.27 49.45,34.02 46.66,34.02 46.23,33.59 v1(46.22,33.59)
IO_L23_35_SPI_ENB: length 24.7
  TOP w0.14: v6(66,32.89) U17.K6 ; U1.C11 v1(45.22,33.59)
  L6_SIG w0.095: v6(66,32.89) 65.82,32.89 64.7,34.02 63.81,34.02 63.03,34.79 60.27,34.79 59.49,34.02 57.96,34.02 56.44,32.49 54.79,32.49 54.54,32.74 54.14,32.74 54.02,32.62 48.57,32.62 47.55,33.63 47.55,33.73 47.36,33.93 45.56,33.93 v1(45.22,33.59)
IO_L24_12_JX4_N: length 73.3
  TOP w0.089: U1.W15 v1(28.22,28.59)
  L6_SIG w0.089: v1(84.51,45.07) 84.76,45.19 84.89,45.19 85.12,44.96 85.12,44.53 84.72,44.14 60.11,44.14 58.87,42.91 56.79,42.91 56.45,42.57 54.49,42.57 54.41,42.65 52.85,42.65 52.49,43.01 50.45,43.01 50.35,42.91 49.18,42.91 48.06,44.03 48.06,44.03 47.91,44.18 44.9,44.18 44.55,43.83 44.55,43.45 44.35,43.25 43.97,43.25 43.55,42.83 43.55,42.45 43.35,42.25 42.97,42.25 42.55,41.83 42.55,41.45 42.35,41.25 41.97,41.25 41.55,40.83 41.55,40.45 41.35,40.25 40.97,40.25 40.55,39.83 40.55,39.45 40.35,39.25 39.97,39.25 39.55,38.83 39.55,38.45 39.35,38.25 38.97,38.25 38.55,37.83 38.55,37.45 38.35,37.25 37.97,37.25 37.55,36.83 37.55,36.45 37.35,36.25 36.97,36.25 36.55,35.83 36.55,35.45 36.35,35.25 35.97,35.25 35.55,34.83 35.55,34.45 35.35,34.25 34.98,34.25 33.55,32.82 33.55,32.45 33.35,32.25 32.97,32.25 32.55,31.83 32.55,31.45 32.35,31.25 31.85,31.25 31.19,30.59 30.28,30.59 29.62,29.93 29.62,28.59 29.62,28.59 29.62,28.51 29.29,28.18 28.45,28.18 28.28,28.01 28.03,28.01 27.87,28.18 27.87,28.43 27.99,28.56 28.18,28.56 v1(28.22,28.59)
  BOTTOM w0.089: v1(84.51,45.07) 84.67,45.23 84.89,45.23 85.15,44.97 JX4.15
IO_L24_12_JX4_P: length 73.2
  TOP w0.089: U1.W16 v1(28.22,27.59)
  L6_SIG w0.089: v1(84.51,45.7) 84.79,45.45 84.99,45.45 85.37,45.07 85.37,44.43 84.83,43.89 60.21,43.89 58.98,42.65 56.89,42.65 56.56,42.32 54.38,42.32 54.3,42.4 52.6,42.4 52.52,42.32 52.24,42.32 52.21,42.34 50.45,42.34 50.14,42.65 49.07,42.65 47.8,43.92 45,43.92 44.81,43.73 44.81,43.34 44.46,43 44.08,43 43.81,42.73 43.81,42.34 43.46,42 43.08,42 42.81,41.73 42.81,41.34 42.46,41 42.08,41 41.81,40.73 41.81,40.34 41.46,40 41.08,40 40.81,39.73 40.81,39.34 40.46,39 40.08,39 39.81,38.73 39.81,38.34 39.46,38 39.08,38 38.81,37.73 38.81,37.34 38.46,37 38.08,37 37.81,36.73 37.81,36.34 37.46,36 37.08,36 36.81,35.73 36.81,35.34 36.46,35 36.08,35 35.81,34.73 35.81,34.34 35.46,34 35.08,34 33.81,32.72 33.81,32.34 33.46,32 33.08,32 32.81,31.73 32.81,31.34 32.46,31 31.96,31 31.29,30.33 30.38,30.33 29.88,29.83 29.88,28.49 29.87,28.49 29.87,28.41 29.39,27.93 28.55,27.93 v1(28.22,27.59)
  BOTTOM w0.089: JX4.13 85.21,45.77 84.89,45.45 84.76,45.45 v1(84.51,45.7)
IO_L24_13_JX2_N: length 74.3
  TOP w0.089: U1.AA18 v1(26.22,25.59)
  L15_SIG w0.089: v1(55.42,3.79) 55.42,3.54 55.3,3.41 55.17,3.41 55.04,3.54 55.04,3.92 54.92,4.05 54.79,4.05 54.44,3.69 54.44,3.38 55.17,2.65 55.96,2.65 56.17,2.44 56.45,2.44 56.66,2.65 58.09,2.65 60.12,4.68 60.12,5.7 58.6,7.22 58.6,7.66 58.54,7.72 58.54,8.97 58.55,8.99 58.55,9.26 58.54,9.28 58.54,9.5 57.64,10.4 57.48,10.4 56.95,10.93 56.95,12.43 56.57,12.81 55.3,12.81 54.92,12.43 54.92,12.32 54.39,11.79 50.34,11.79 49.84,12.3 49.33,12.3 47.68,13.95 40.31,13.95 38.49,15.77 38.08,15.77 36.64,15.77 36.56,15.86 27.74,15.86 27.1,15.22 26.15,15.22 25.98,15.39 25.97,15.39 25.62,15.74 25.62,16.74 25.97,17.08 26.25,17.08 26.55,17.38 26.55,20.67 26.6,20.71 26.6,20.8 26.63,20.83 26.63,20.83 26.97,21.18 28.35,21.18 28.62,21.45 28.62,23.62 28.55,23.69 28.55,23.73 28.35,23.92 28.32,23.92 28.24,24 27.97,24 27.63,24.34 27.63,24.69 27.39,24.93 26.88,24.93 26.69,25.11 26.69,25.26 26.37,25.59 v1(26.22,25.59)
  BOTTOM w0.089: JX2.76 60.73,5.7 60.47,5.44 60.47,4.72 59.96,4.21 56.73,4.21 56.44,3.92 55.55,3.92 v1(55.42,3.79)
IO_L24_13_JX2_P: length 74.2
  TOP w0.089: U1.Y18 v1(27.22,25.59)
  L15_SIG w0.089: v1(55.42,4.3) 54.68,4.3 54.18,3.8 54.18,3.59 54.18,3.28 55.06,2.39 55.86,2.39 56.07,2.19 56.56,2.19 56.77,2.39 58.2,2.39 60.38,4.58 60.38,5.8 58.85,7.33 58.85,7.76 58.79,7.82 58.79,8.86 58.81,8.88 58.81,9.37 58.79,9.39 58.79,9.6 57.74,10.65 57.58,10.65 57.2,11.03 57.2,12.53 56.67,13.06 55.19,13.06 54.66,12.53 54.66,12.43 54.28,12.05 50.45,12.05 49.94,12.55 49.43,12.55 47.78,14.21 40.42,14.21 39.75,14.87 39.01,15.61 38.59,16.03 38.18,16.03 36.74,16.03 36.66,16.11 27.63,16.11 27,15.48 26.26,15.48 26.09,15.65 26.07,15.65 25.88,15.84 25.88,16.63 26.07,16.83 26.36,16.83 26.81,17.28 26.81,20.57 26.85,20.61 26.85,20.69 26.88,20.72 26.88,20.73 27.08,20.92 28.46,20.92 28.88,21.34 28.88,23.72 28.81,23.8 28.81,23.83 28.46,24.18 28.42,24.18 28.35,24.25 28.08,24.25 27.88,24.45 27.88,24.8 27.5,25.18 26.98,25.18 26.95,25.22 26.95,25.32 v1(27.22,25.59)
  BOTTOM w0.089: JX2.74 59.93,5.77 60.25,5.44 60.25,4.81 59.87,4.43 56.64,4.43 56.35,4.13 55.59,4.13 v1(55.42,4.3)
IO_L24_33_JX1_N: length 72.4
  TOP w0.089: U1.K7 v1(38.22,37.59)
  L7_SIG w0.089: v1(38.22,37.59) 38.41,37.4 38.41,37.32 38.22,37.13 37.86,37.13 37.77,37.22 37.77,37.31 37.81,37.34 37.81,43.97 38.19,44.35 40.04,44.35 40.57,44.88 40.57,47.55 40.55,47.57 40.55,47.9 40.57,47.92 40.57,48.64 40.8,48.88 41.35,48.88 41.58,48.64 41.58,44.88 42.11,44.35 42.77,44.35 43.99,45.57 45.14,45.57 45.52,45.96 45.52,47.1 46.41,47.99 47.68,47.99 48.95,49.26 48.95,49.51 49.33,49.89 49.36,49.89 49.44,49.98 52.77,49.98 52.85,49.89 61.72,49.89 61.74,49.91 61.93,49.91 62.28,50.26 62.28,50.79 61.91,51.16 52.63,51.16 52.25,51.54 52.25,54.19 51.72,54.72 50.75,54.72 50.22,54.19 50.22,51.54 49.84,51.16 46.81,51.16 46.28,50.63 46.28,49.26 46.03,49 45.39,49 45.26,49.13 45.26,49.38 v1(45.52,49.64)
  BOTTOM w0.089: JX1.38 45.53,50.32 45.23,50.02 45.23,49.93 v1(45.52,49.64)
IO_L24_33_JX1_P: length 72.4
  TOP w0.089: U1.K8 v1(38.22,36.59)
  L7_SIG w0.089: v1(38.22,36.59) 38.22,36.69 38.03,36.88 37.75,36.88 37.52,37.11 37.52,37.41 37.55,37.45 37.55,44.07 38.08,44.6 39.93,44.6 40.31,44.98 40.31,47.44 40.29,47.46 40.29,48 40.31,48.02 40.31,48.75 40.69,49.13 41.45,49.13 41.84,48.75 41.84,44.98 42.22,44.6 42.66,44.6 43.89,45.83 45.03,45.83 45.26,46.06 45.26,47.2 46.3,48.24 47.57,48.24 48.69,49.36 48.69,49.62 49.22,50.15 49.25,50.15 49.34,50.23 52.88,50.23 52.96,50.15 61.61,50.15 61.63,50.16 61.82,50.16 62.03,50.37 62.03,50.69 61.81,50.91 52.52,50.91 52,51.44 52,54.08 51.61,54.46 50.85,54.46 50.47,54.08 50.47,51.44 49.94,50.91 46.92,50.91 46.53,50.53 46.53,49.15 46.13,48.75 45.29,48.75 45.01,49.03 45.01,49.38 v1(44.76,49.64)
  BOTTOM w0.089: JX1.36 44.73,50.3 45.01,50.02 45.01,49.89 v1(44.76,49.64)
IO_L24_34_CTRL_IN2: length 19
  TOP w0.14: U1.B2 v1(46.22,42.59) ; U22.11 v1(54.28,31.48)
  L15_SIG w0.095: v1(54.28,31.48) 52.88,32.87 52.88,40.4 52.58,40.71 48.73,40.71 47.36,42.08 46.6,42.08 46.22,42.46 v1(46.22,42.59)
IO_L24_34_CTRL_IN3: length 17.7
  TOP w0.14: U22.10 54.54,31.98 54.28,32.24 v1(54.28,32.4) ; U1.A2 v1(47.22,42.59)
  L15_SIG w0.095: v1(54.28,32.4) 53.27,33.42 53.27,40.75 52.5,41.51 49.71,41.51 49.54,41.68 48.81,41.68 48.49,42 47.8,42 v1(47.22,42.59)
IO_L24_35_SPI_DI: length 27.9
  TOP w0.14: v6(67.6,32.09) U17.J4 ; U1.A13 v1(47.22,31.59)
  L14_SIG w0.095: v1(47.22,31.59) 48.07,31.59 48.31,31.35 49.84,31.35 50.63,30.56 53.3,30.56 53.84,31.1 55.04,31.1 55.17,30.97 58.12,30.97 58.39,30.7 58.39,30.07 58.59,29.87 59.45,29.87 59.49,29.83 64.44,29.83 64.82,30.21 65.58,30.21 66.35,29.45 66.73,29.45 67.3,28.88 67.3,28.77 67.47,28.59 67.72,28.59 67.9,28.77 67.9,31.42 67.6,31.72 v6(67.6,32.09)
IO_L24_35_SPI_DO: length 28.5
  TOP w0.14: v6(66,33.69) U17.L6 ; U1.A12 v1(47.22,32.59)
  L6_SIG w0.095: v6(66,33.69) 65.65,33.69 63.81,35.54 60.63,35.54 59.87,34.78 58.35,34.78 56.3,32.74 55.18,32.74 54.54,33.38 48.69,33.38 47.83,34.25 47.07,34.25 47.05,34.27 46.38,34.27 46.36,34.25 46.07,34.25 46.05,34.27 45.38,34.27 45.36,34.25 45.11,34.25 44.76,33.89 44.76,33.38 45.01,33.13 46.68,33.13 v1(47.22,32.59)
J3-9: length 110.8
  TOP w0.14: v1(78.67,59.43) 78.67,58.66 78.48,58.47 U5.7 ; J3.9 15.95,25.87 15.42,26.4 v1(15.04,26.4)
  L14_SIG w0.095: v1(78.67,59.43) 78.67,59.04 78.41,58.78 78.16,58.78 76.51,57.13 75.62,57.13 75.11,57.64 73.33,57.64 72.57,58.4 70.66,58.4 69.14,56.88 66.28,56.88 66.23,56.83 65.98,56.83 65.94,56.88 57.33,56.88 55.81,55.35 47.04,55.35 46.28,54.59 38.53,54.59 36.76,52.81 36.76,49 35.74,47.99 32.31,47.99 28.55,44.23 28.55,42.33 28.25,42.02 18.34,42.02 17.96,41.64 17.96,39.48 17.58,39.1 17.58,32.62 16.05,31.1 14.02,31.1 13.51,30.59 13.51,27.92 v1(15.04,26.4)
  L15_SIG w0.095: v1(15.04,26.4) 14.15,26.4 13.64,25.89 7.8,25.89 7.29,25.38 6.4,25.38 6.15,25.64 4.5,25.64 v1(1.83,28.3)
  BOTTOM w0.14: 3.1,28.3 3.08,28.32 1.85,28.32 v1(1.83,28.3)
JTAG_TCK: length 27.8
  TOP w0.14: U1.W12 v1(28.22,32.59)
  L15_SIG w0.095: v1(28.22,32.59) 27.88,32.93 27.88,43.81 30.15,46.08 30.15,51.04 31.13,52.01 v3(31.13,56.28)
  L19_GND w0.203: v4(31.13,56.79) v3(31.13,56.28)
  BOTTOM w0.14: JX1.1 v4(31.13,56.79)
JTAG_TDI: length 19.5
  TOP w0.14: U1.V11 v1(29.22,33.59)
  L7_SIG w0.095: v1(29.22,33.59) 29.88,34.25 30.36,34.25 30.56,34.45 30.56,34.93 30.88,35.25 30.88,46.17 31.93,47.22 v1(31.93,49.51)
  BOTTOM w0.14: JX1.4 v1(31.93,49.51)
JTAG_TDO: length 25.9
  TOP w0.14: U1.W10 v1(28.22,34.59)
  L15_SIG w0.095: v3(31.93,56.12) 31.93,51.16 30.66,49.89 30.66,45.22 29.37,43.93 29.07,43.93 28.88,43.73 28.88,43.54 28.56,43.22 28.56,34.93 v1(28.22,34.59)
  L19_GND w0.203: v4(31.93,56.75) v3(31.93,56.12)
  BOTTOM w0.14: JX1.3 v4(31.93,56.75)
JTAG_TMS: length 19.8
  TOP w0.14: U1.W11 v1(28.22,33.59)
  L7_SIG w0.095: v1(31.13,49.55) 31.13,47.06 30.53,46.46 30.53,44.58 30.56,44.56 30.56,35.45 30.36,35.25 30.07,35.25 29.56,34.73 29.56,34.45 29.36,34.25 28.88,34.25 v1(28.22,33.59)
  BOTTOM w0.14: JX1.2 v1(31.13,49.55)
JX3_SD1_CDN: length 94.5
  TOP w0.14: U5.9 77.25,57.91 v1(76.89,58.27)
  L14_SIG w0.095: v1(76.89,58.27) 74.6,58.27 73.46,59.42 70.66,59.42 70.03,58.78 56.57,58.78 54.68,56.9 54.68,56.71 54.45,56.47 54.26,56.47 53.52,55.73 46.79,55.73 46.03,54.97 35.61,54.97 34.34,53.7 34.34,50.53 30.66,46.84 29.64,46.84 26.55,43.76 26.55,43.45 26.27,43.16 19.48,43.16 19.36,43.29 18.91,43.29 18.89,43.27 18.45,43.27 17.2,42.02 17.2,33.26 16.44,32.49 13.26,32.49 12.24,31.48 12.24,29.32 10.3,27.37 v1(6.83,27.37)
  BOTTOM w0.14: JX3.41 v1(6.83,27.37)
JX_MGTAVCC: length 19.6
  TOP w0.305: 7.55,35.16 8.05,35.16 Q8.2 Q8.5 8.05,37.45 ; 7.55,35.16 Q8.1 Q8.6 7.55,37.45 8.05,37.45 ; 7.55,35.16 7.16,35.16 6.91,35.41 v1(6.78,35.41) v1(6.78,34.78) ; 8.05,37.45 8.05,37.7 8.58,38.23 U7.3
  BOTTOM w0.508: 6.67,14.57 6.67,15.37 JX3.11 ; 6.67,14.57 6.67,13.77 ; 6.67,14.57 JX3.9 ; v1(5.26,12.43) v1(5.89,12.43) 6.44,12.97 6.66,12.97 ; JX3.7 6.67,13.77 ; 6.67,13.77 6.66,13.77 6.66,12.97 ; 6.66,12.97 JX3.5
JX_MGTAVTT: length 28.4
  TOP w0.305: Q7.1 Q7.6 Q7.5 v1(10.85,36.43) Q7.2 v1(10.85,37.57) 10.34,38.08 9.45,38.08 9.07,38.46 9.07,39.76 U7.4
  L4_SIG w0.508: v1(10.85,36.43) 10.97,36.43 11.61,35.8 11.61,25.51 13.77,23.35 v1(14.91,23.35)
  BOTTOM w0.406: JX3.32 14.89,23.37 v1(14.91,23.35) v1(14.91,22.71) 14.77,22.57 JX3.30
JX_VCCO_12: length 13.3
  TOP w0.406: Q11.PAD1 13.64,36.75 Q11.5 ; Q11.PAD1 12.99,36.1 v2(12.99,35.52) ; Q11.PAD1 12.99,36.76 Q11.6 12.99,37.83 12.61,38.21 R70.1 ; Q11.PAD1 13.64,36.11 v2(13.64,35.52)
  L2_GND w0.381: v3(13.51,34.78) 13.64,34.91 v2(13.64,35.52) ; v3(13.01,34.78) 12.99,34.79 v2(12.99,35.52)
  BOTTOM w0.305: JX1.78 61.53,49.89 v5(61.9,49.51) 62.33,49.94 JX1.80
  BOTTOM w0.508: JX1.79 62.33,53.87 v5(61.52,53.07)
JX_VCCO_12_SEQ: length 2.1
  TOP w0.14: 10.85,38.59 R69.1
  TOP w0.254: 10.85,38.59 11.23,38.21 R70.2 ; R69.1 10.78,39.03 10.58,39.24 U7.7
JX_VCCO_13: length 125.6
  TOP w0.254: Q9.PAD1 16.04,36.86 Q9.1 16.04,35.18 ; Q9.PAD1 16.69,36.87 16.69,36.49 ; Q9.PAD1 16.04,37.52 Q9.6 ; Q9.PAD1 16.69,37.51 Q9.5 Q9.6 ; v1(10.59,34.14) 10.88,33.86 ; Q9.6 16.04,38.38 15.45,38.97 R72.1
  TOP w0.305: 16.69,36.49 Q9.2 16.69,35.16
  TOP w0.406: 10.88,33.86 12.4,33.86 12.88,33.38 14.91,33.38 15.55,34.02 15.55,34.68 16.04,35.18
  L3_SIG w0.305: v1(9.54,28.97) 10.34,28.97 10.34,33.89 v1(10.59,34.14)
  L14_SIG w0.254: v3(69.52,7.47) 68.51,6.46 63.93,6.46 62.92,7.47 61.65,7.47 60.89,6.71 56.57,6.71 55.68,5.82 32.69,5.82 31.68,4.81 29.98,4.81 29.94,4.85 29.1,4.85 28.42,5.52 27.74,5.52 27.48,5.27 26.17,5.27 24.94,4.05 22.32,4.05 21.77,3.49 21.1,3.49 21.09,3.5 20.33,3.5 19.9,3.93 19.9,4.6 19.66,4.85 18.18,4.85 16.18,6.84 16.18,7.73 14.15,9.76 13.9,9.76 13.39,10.27 13.39,10.57 13.35,10.6 13.35,11.02 13.35,11.07 13.26,11.16 13.26,11.16 13.13,11.28 13.13,13.82 11.86,15.09 11.86,16.62 10.85,17.63 10.59,17.63 10,18.23 9.49,18.23 7.8,19.92 6.02,19.92 4.24,18.14 3.23,18.14 2.64,18.73 2.64,18.85 2.64,19.04 2.64,19.04 2.59,19.09 2.59,21.06 3.74,22.21 3.74,27.29 5.8,29.36 6.45,29.36 6.49,29.32 9.2,29.32 v1(9.54,28.97)
  L19_GND w0.102: v3(69.52,7.47) 69.39,7.6 v4(69.39,7.98)
  BOTTOM w0.102: JX2.98 69.53,7.34 69.27,7.6 69.27,7.86 v4(69.39,7.98)
  BOTTOM w0.508: JX3.46 v1(9.54,28.97) JX3.45
